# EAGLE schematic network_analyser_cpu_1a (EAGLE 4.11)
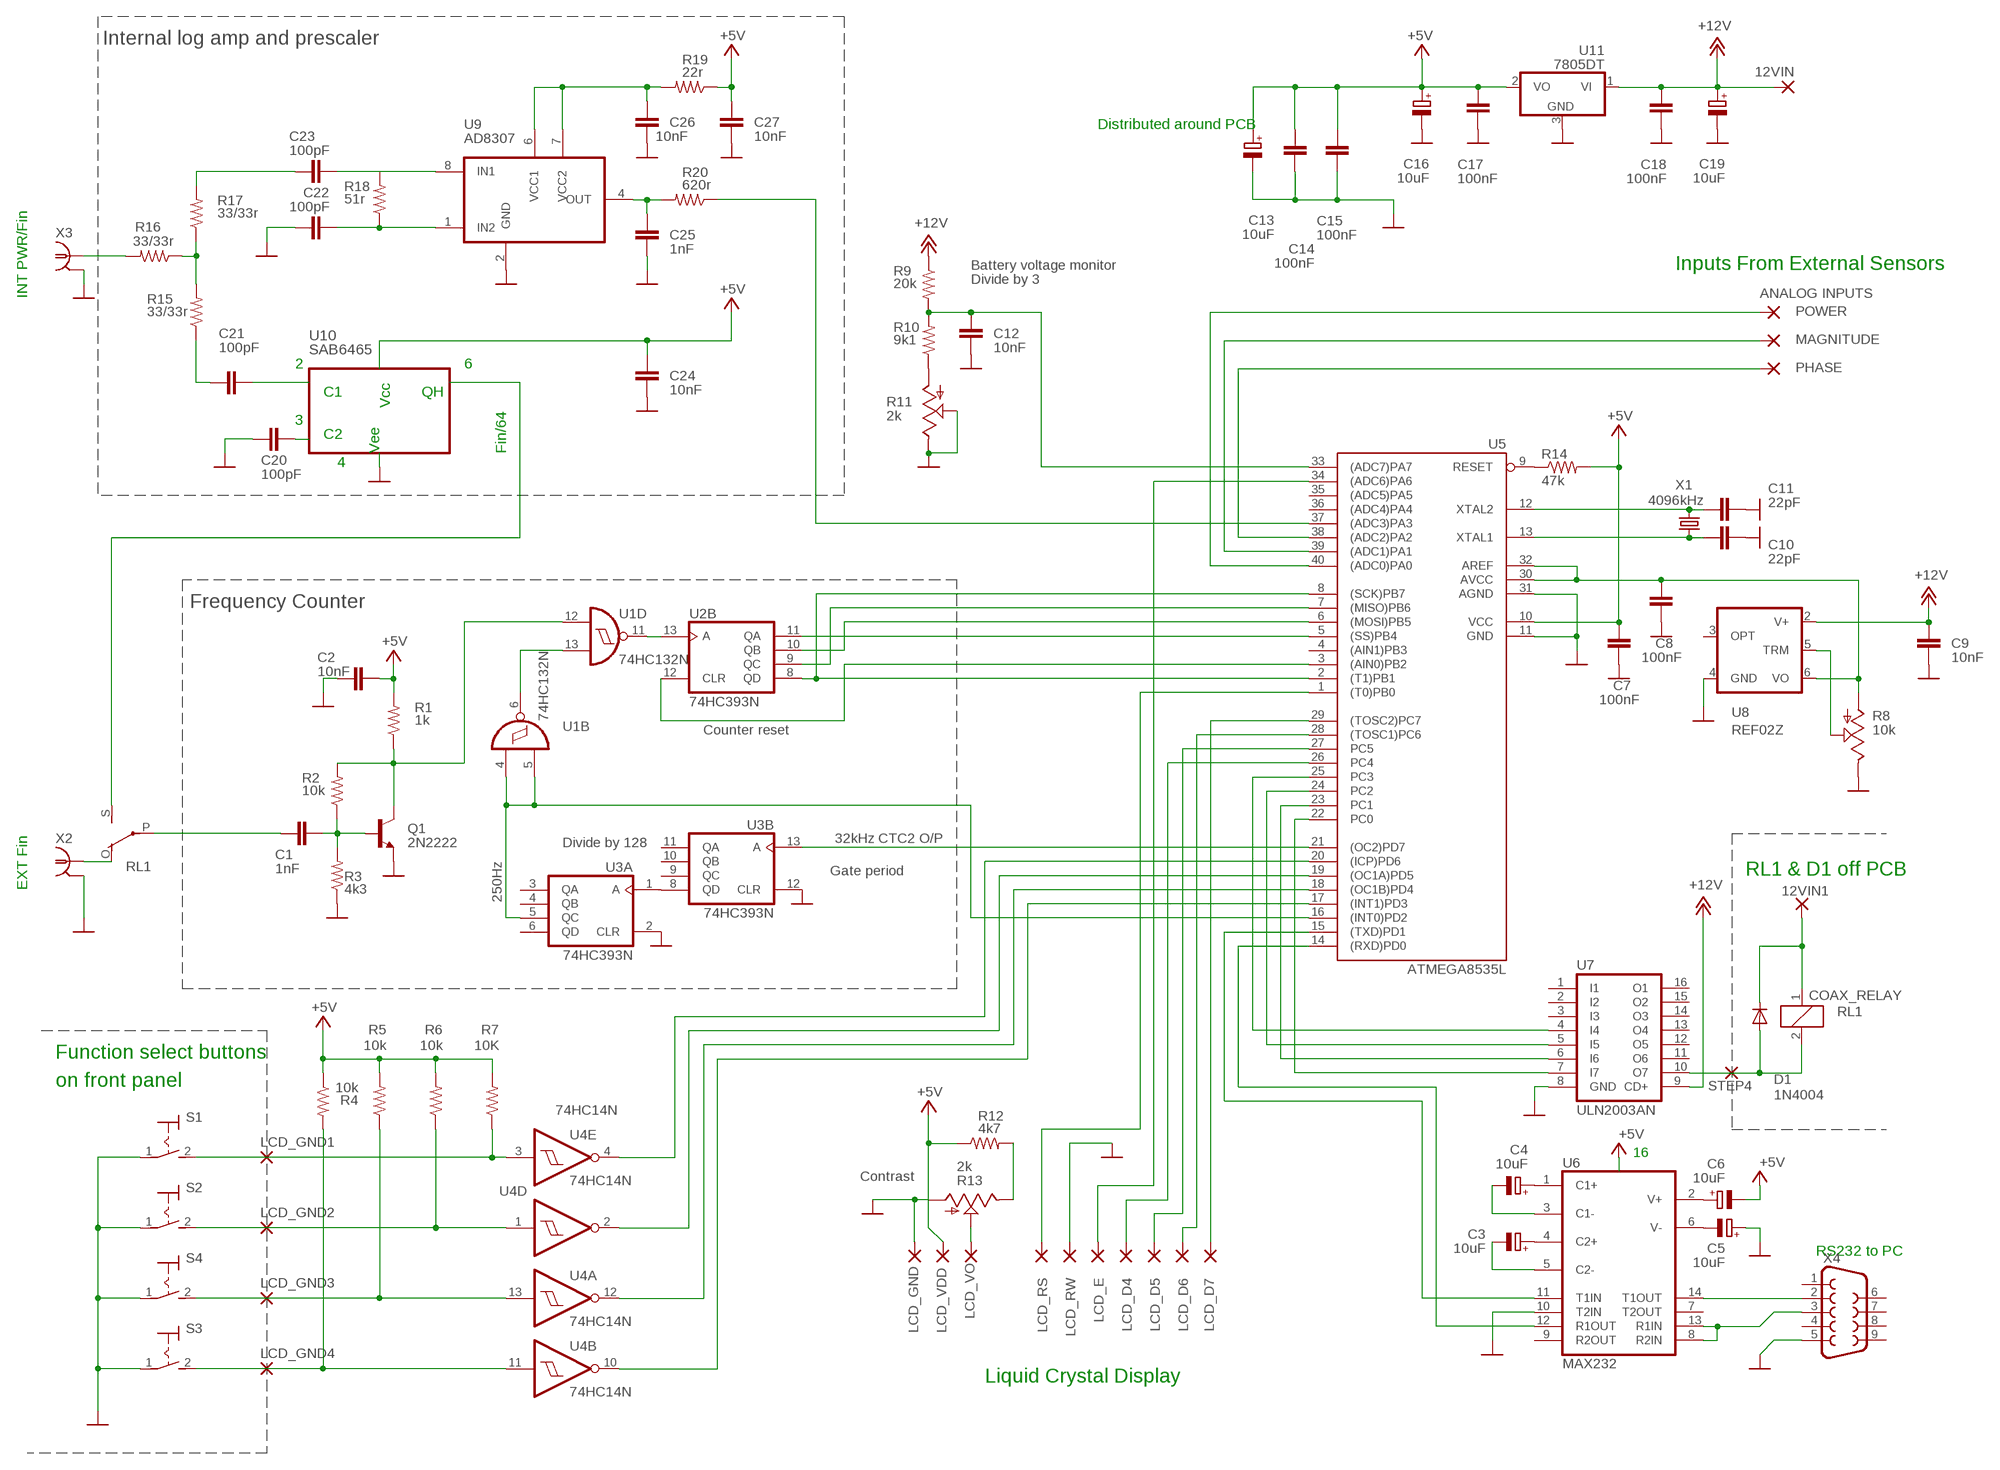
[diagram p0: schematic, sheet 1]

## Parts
12VIN  2,54/0,8  [2,54/0,8]
12VIN1  2,54/0,8  [2,54/0,8]
C1  1nF  C5/3  [C5B3]
C2  10nF  C5/3  [C5B3]
C3  10uF  CPOL-EUE2.5-6  [E2,5-6]
C4  10uF  CPOL-EUE2.5-6  [E2,5-6]
C5  10uF  CPOL-EUE2.5-6  [E2,5-6]
C6  10uF  CPOL-EUE2.5-6  [E2,5-6]
C7  100nF  C-EUC1206  [C1206]
C8  100nF  C-EUC1206  [C1206]
C9  10nF  C5/3  [C5B3]
C10  22pF  C5/3  [C5B3]
C11  22pF  C5/3  [C5B3]
C12  10nF  C5/3  [C5B3]
C13  10uF  CPOL-EUE5-6  [E5-6]
C14  100nF  C-EUC1206  [C1206]
C15  100nF  C-EUC1206  [C1206]
C16  10uF  CPOL-EUE5-6  [E5-6]
C17  100nF  C-EUC1206  [C1206]
C18  100nF  C-EUC1206  [C1206]
C19  10uF  CPOL-EUE5-6  [E5-6]
C20  100pF  C5/3  [C5B3]
C21  100pF  C5/3  [C5B3]
C22  100pF  C5/3  [C5B3]
C23  100pF  C5/3  [C5B3]
C24  10nF  C5/3  [C5B3]
C25  1nF  C5/3  [C5B3]
C26  10nF  C5/3  [C5B3]
C27  10nF  C5/3  [C5B3]
D1  1N4004  [DO41-10]
LCD_D4  1,6/0,8  [1,6/0,8]
LCD_D5  1,6/0,8  [1,6/0,8]
LCD_D6  1,6/0,8  [1,6/0,8]
LCD_D7  1,6/0,8  [1,6/0,8]
LCD_E  1,6/0,8  [1,6/0,8]
LCD_GND  1,6/0,8  [1,6/0,8]
LCD_GND1  1,6/0,8  [1,6/0,8]
LCD_GND2  1,6/0,8  [1,6/0,8]
LCD_GND3  1,6/0,8  [1,6/0,8]
LCD_GND4  1,6/0,8  [1,6/0,8]
LCD_RS  1,6/0,8  [1,6/0,8]
LCD_RW  1,6/0,8  [1,6/0,8]
LCD_VDD  1,6/0,8  [1,6/0,8]
LCD_VO  1,6/0,8  [1,6/0,8]
MAGNITUDE  2,54/0,8  [2,54/0,8]
PHASE  2,54/0,8  [2,54/0,8]
POWER  2,54/0,8  [2,54/0,8]
Q1  2N2222  [TO18]
R1  1k  R-US_0309/V  [0309V]
R2  10k  R-US_0309/V  [0309V]
R3  4k3  R-US_0309/V  [0309V]
R4  10k  R-US_0309/V  [0309V]
R5  10k  R-US_0309/V  [0309V]
R6  10k  R-US_0309/V  [0309V]
R7  10K  R-US_0309/V  [0309V]
R8  10k  TRIM_US-RJ9W  [RJ9W]
R9  20k  R-US_0204/7  [0204/7]
R10  9k1  R-US_0204/7  [0204/7]
R11  2k  TRIM_US-RJ9W  [RJ9W]
R12  4k7  R-US_0204/7  [0204/7]
R13  2k  TRIM_US-LI10  [LI10]
R14  47k  R-US_0309/V  [0309V]
R15  33/33r  R-US_0309/V  [0309V]
R16  33/33r  R-US_0309/V  [0309V]
R17  33/33r  R-US_0309/V  [0309V]
R18  51r  R-US_0309/V  [0309V]
R19  22r  R-US_0309/V  [0309V]
R20  620r  R-US_0309/V  [0309V]
RL1  COAX_RELAY  E3206L  [E3206L]
S1  MS243  [MS243]
S2  MS243  [MS243]
S3  MS243  [MS243]
S4  MS243  [MS243]
STEP4  2,54/0,8  [2,54/0,8]
U1  74HC132N  [DIL14]
U2  74HC393N  74LS393N  [DIL14]
U3  74HC393N  74393N  [DIL14]
U4  74HC14N  [DIL14]
U5  ATMEGA8535L  AT90LS8535P  [DIL40]
U6  MAX232  [DIL16]
U7  ULN2003AN  [DIL16]
U8  REF02Z  [DIL08]
U9  AD8307  [DIL08]
U11  7805DT  [TO252]
X1  4096kHz  HC49/S  [HC49/S]
X2  A1944-50  [A1944]
X3  A1944-50  [A1944]
X4  F09D  [F09D]

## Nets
+5V: C2.2 C6.- C7.1 C13.+ C14.1 C15.1 C16.+ C17.1 C24.2 C27.2 LCD_VDD.1(P) R1.2 R4.1 R5.2 R6.2 R7.2 R12.1 R14.2 R19.1 U5.10(VCC) U11.2(VO)
+12V: 12VIN.1(P) C9.2 C18.1 C19.+ R9.1 U7.9(CD+) U8.2(V+) U11.1(VI)
GND: C2.1 C5.+ C7.2 C8.2 C9.1 C10.2 C11.2 C12.1 C13.- C14.2 C15.2 C16.- C17.2 C18.2 C19.- C20.1 C22.1 C24.1 C25.1 C26.1 C27.1 LCD_GND.1(P) LCD_RW.1(P) Q1.1(E) R3.1 R8.E R11.E R11.S R13.A S1.1(P) S2.1(P) S3.1(P) S4.1(P) U3.2(A:CLR) U3.12(B:CLR) U5.11(GND) U5.31(AGND) U6.10(T2IN) U7.8(GND) U8.4(GND) U9.2(GND) U11.3(GND) X2.2(GND) X3.2(GND) X4.5
N$1: U1.11(D:O) U2.13(B:A)
N$2: U2.12(B:CLR) U5.3((AIN0)PB2)
N$3: C25.2 R20.2 U9.4(OUT)
N$4: LCD_GND2.1(P) R6.1 S2.2(S) U4.1(D:I)
N$5: U3.1(A:A) U3.8(B:QD)
N$6: U2.11(B:QA) U5.5((SS)PB4)
N$7: U2.10(B:QB) U5.6((MOSI)PB5)
N$8: U2.9(B:QC) U5.7((MISO)PB6)
N$9: C11.1 U5.12(XTAL2) X1.2
N$10: LCD_GND1.1(P) R7.1 S1.2(S) U4.3(E:I)
N$11: R16.2 X3.1
N$12: LCD_GND3.1(P) R5.1 S4.2(S) U4.13(A:I)
N$13: U3.13(B:A) U5.21((OC2)PD7)
N$14: C10.1 U5.13(XTAL1) X1.1
N$15: U1.6(B:O) U1.13(D:I1)
N$16: R8.S U8.5(TRM)
N$17: LCD_RS.1(P) U5.1((T0)PB0)
N$18: LCD_VO.1(P) R13.S
N$19: U1.4(B:I0) U1.5(B:I1) U3.5(A:QC) U5.16((INT0)PD2)
N$20: C8.1 R8.A U5.30(AVCC) U5.32(AREF) U8.6(VO)
N$21: R12.2 R13.E
N$22: R10.1 R11.A
N$23: U5.15((TXD)PD1) U6.11(T1IN)
N$24: R14.1 U5.9(RESET)
N$25: C1.1 RL1.P(2:P)
N$26: C12.2 R9.2 R10.2 U5.33((ADC7)PA7)
N$27: RL1.O(2:O) X2.1
N$28: 12VIN1.1(P) D1.C RL1.1
N$29: C23.2 U9.8(IN1)
N$30: C22.2 R18.1 U9.1(IN2)
N$31: C21.1 R15.1
N$32: LCD_D7.1(P) U5.29((TOSC2)PC7)
N$33: LCD_D6.1(P) U5.28((TOSC1)PC6)
N$34: LCD_D5.1(P) U5.27(PC5)
N$35: LCD_D4.1(P) U5.26(PC4)
N$36: LCD_E.1(P) U5.34((ADC6)PA6)
N$37: U5.14((RXD)PD0) U6.12(R1OUT)
N$38: D1.A RL1.2 STEP4.1(P) U7.10(O7)
N$39: R15.2 R16.1 R17.1
N$40: C6.+ U6.2(V+)
N$41: C23.1 R17.2
N$42: R20.1 U5.37((ADC3)PA3)
N$43: C21.2
N$44: C20.2
N$45: RL1.S(2:S)
N$46: PHASE.1(P) U5.38((ADC2)PA2)
N$47: MAGNITUDE.1(P) U5.39((ADC1)PA1)
N$48: POWER.1(P) U5.40((ADC0)PA0)
N$49: C5.- U6.6(V-)
N$50: C3.+ U6.4(C2+)
N$51: U5.22(PC0) U7.7(I7)
N$52: U5.23(PC1) U7.6(I6)
N$53: U4.4(E:O) U5.20((ICP)PD6)
N$54: U5.24(PC2) U7.5(I5)
N$55: C4.+ U6.1(C1+)
N$56: U5.25(PC3) U7.4(I4)
N$57: C1.2 Q1.2(B) R2.1 R3.2
N$58: C4.- U6.3(C1-)
N$59: C3.- U6.5(C2-)
N$60: U6.14(T1OUT) X4.2
N$61: U6.8(R2IN) U6.13(R1IN) X4.3
N$62: C26.2 R19.2 U9.6(VCC1) U9.7(VCC2)
N$65: LCD_GND4.1(P) R4.2 S3.2(S) U4.11(B:I)
N$66: Q1.3(C) R1.1 R2.2 U1.12(D:I0)
N$68: U4.10(B:O) U5.17((INT1)PD3)
N$83: U2.8(B:QD) U5.2((T1)PB1) U5.8((SCK)PB7)
N$92: U4.12(A:O) U5.18((OC1B)PD4)
N$95: U4.2(D:O) U5.19((OC1A)PD5)
Unconnected: R18.2 U1.1(A:I0) U1.2(A:I1) U1.3(A:O) U1.8(C:O) U1.9(C:I0) U1.10(C:I1) U2.1(A:A) U2.2(A:CLR) U2.3(A:QA) U2.4(A:QB) U2.5(A:QC) U2.6(A:QD) U3.3(A:QA) U3.4(A:QB) U3.6(A:QD) U3.9(B:QC) U3.10(B:QB) U3.11(B:QA) U4.5(F:I) U4.6(F:O) U4.8(C:O) U4.9(C:I) U5.4((AIN1)PB3) U5.35((ADC5)PA5) U5.36((ADC4)PA4) U6.7(T2OUT) U6.9(R2OUT) U7.1(I1) U7.2(I2) U7.3(I3) U7.11(O6) U7.12(O5) U7.13(O4) U7.14(O3) U7.15(O2) U7.16(O1) U8.3(OPT) X4.1 X4.4 X4.6 X4.7 X4.8 X4.9

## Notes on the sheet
- Internal log amp and prescaler
- Distributed around PCB
- Battery voltage monitor | Inputs From External Sensors
- Divide by 3
- INT PWR/Fin | ANALOG INPUTS
- U10
- SAB6465
- 2 | 6
- Vcc
- C1 | QH
- 3
- C2
- Vee | Fin/64
- 4
- Frequency Counter
- Counter reset
- 32kHz CTC2 O/P
- Divide by 128
- 250Hz | Relay off PCB
- Gate period | RL1 & D1 off PCB
- EXT Fin
- Function select buttons
- on front panel | on front panel
- 16
- Contrast
- RS232 to PC
- Liquid Crystal Display

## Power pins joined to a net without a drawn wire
GND: U1.7(P:GND) U2.7(P:GND) U3.7(P:GND) U4.7(P:GND) U6.15(GND) X2.3(GND) X2.4(GND) X2.5(GND) X3.3(GND) X3.4(GND) X3.5(GND)
VCC: U1.14(P:VCC) U2.14(P:VCC) U3.14(P:VCC) U4.14(P:VCC) U6.16(VCC)

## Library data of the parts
12VIN 12VIN1 MAGNITUDE PHASE POWER STEP4 = wirepad:2,54/0,8: THROUGH-HOLE PAD
C1 C2 C9-C12 C20-C27 = capacitor-wima:C: CAPACITOR
C3-C6 C13 C16 C19 = rcl:CPOL-EU: POLARIZED CAPACITOR, European symbol
C7 C8 C14 C15 C17 C18 = rcl:C-EU: CAPACITOR, European symbol
D1 = diode:1N4004: DIODE
LCD_D4-LCD_D7 LCD_E LCD_GND LCD_GND1-LCD_GND4 LCD_RS LCD_RW LCD_VDD LCD_VO = wirepad:1,6/0,8: THROUGH-HOLE PAD
Q1 = transistor:2N2222: NPN TRANSISTOR
R1-R7 R9 R10 R12 R14-R20 = rcl:R-US_: RESISTOR, American symbol
R8 R11 R13 = pot:TRIM_US-: POTENTIOMETER
RL1 = relay:E3206L: RELAY 1 x switch, Eichhoff/distributor Schukat
S1-S4 = switch:MS243: TOGGLE SWITCH
U1 = 74xx-eu:74*132: Quad 2-input NAND schmitt trigger
U2 U3 = 74xx-us:74*393: Dual 4-bit decade and binary COUNTER
U4 = 74xx-eu:74*14: Hex schmitt trigger INVERTER
U5 = atmel:AT90*8535P: MICROCONTROLLER 8 Kbytes FLASH 512 bytes SRAM 512 bytes EEPROM UART 8-channel 10 bit ADC
U6 = maxim:MAX232: RS232 TRANSEIVER
U7 = uln-udn:ULN2003A: DRIVER ARRAY
U8 = linear:REF02: VOLTAGE REFERENCE
U9 = DEH_special:AD8307: AD8307 LOG AMPLIFIER
U11 = linear:78*: Positive VOLTAGE REGULATOR
X1 = crystal:HC49/S: CRYSTAL
X2 X3 = con-coax:A1944-50: BNC CONNECTOR 50 Ohm distributor Buerklin 78F2475
X4 = con-subd:F09: SUB-D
